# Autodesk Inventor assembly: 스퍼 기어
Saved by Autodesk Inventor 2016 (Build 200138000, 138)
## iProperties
Created: 2018-09
Part Number: 스퍼 기어
Document SubType Name: Assembly
Designer: MYS
Categories: <?xml version="1.0" encoding="UTF-16"?> <MemberInstance><Categories><FamilyTemplate/><ParamToTemplateMap><ParamToTemplate><ParamToTemplate CategoryParameter="//
ClientObjectVersion: 1
Author: MYS
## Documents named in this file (1)
- C:\Users\MYS\Desktop\답안\2단 스퍼기어\디자인 액셀러레이터\스퍼 기어2.iam
